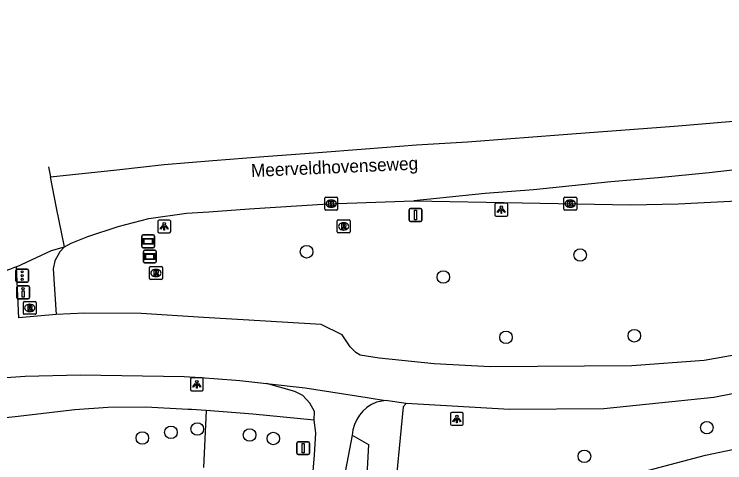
# Model space of a CAD drawing. Extents: x 157663 to 158496, y 379212 to 380934.
# Drawn here: x 158050.2 to 158105.5, y 380860.2 to 380895.1 of the extents above; entities that cross this region are included whole.
import ezdxf

# ---------------------------------------------------------------- set-up
doc = ezdxf.new("R2010")
doc.units = 0
for name, color, linetype in [('IMGEO_Berm_groen', 7, 'Continuous'), ('IMGEO_Boom', 7, 'Continuous'), ('IMGEO_Drukknoppaal', 7, 'Continuous'), ('IMGEO_Fietspad_gesloten', 7, 'Continuous'), ('IMGEO_Kolk', 7, 'Continuous'), ('IMGEO_Lichtpunt', 7, 'Continuous'), ('IMGEO_Openbare_ruimte_label', 7, 'Continuous'), ('IMGEO_Plaatsnaambord', 7, 'Continuous'), ('IMGEO_Rijbaan_regionaal_gesloten', 7, 'Continuous'), ('IMGEO_Rioolput', 7, 'Continuous'), ('IMGEO_Verkeersbordpaal', 7, 'Continuous'), ('IMGEO_Verkeersregelinstallatiepaal', 7, 'Continuous'), ('IMGEO_Voetpad_open', 7, 'Continuous')]:
    doc.layers.add(name, color=color, linetype=linetype)

msp = doc.modelspace()

# ---------------------------------------------------------------- linework, layer by layer
at = {"layer": 'IMGEO_Berm_groen'}
msp.add_lwpolyline([(158065.142, 380864.278), (158064.931, 380859.841)], dxfattribs=at)
at = {"layer": 'IMGEO_Boom'}
for centre in [(158072.959, 380876.644), (158094.236, 380876.394), (158083.597, 380874.678), (158098.449, 380870.11), (158088.471, 380869.981), (158064.452, 380862.854), (158104.093, 380862.957), (158062.405, 380862.587), (158068.523, 380862.386), (158060.18, 380862.153), (158070.369, 380862.108), (158094.569, 380860.723)]:
    msp.add_circle(centre, 0.489, dxfattribs=at)
at = {"layer": 'IMGEO_Drukknoppaal'}
for p, q in [((158050.411, 380873.085), (158050.411, 380873.885)), ((158050.411, 380873.885), (158050.411, 380873.085)), ((158050.511, 380873.985), (158051.301, 380873.985)), ((158051.301, 380873.985), (158050.511, 380873.985)), ((158051.401, 380873.885), (158051.401, 380873.085)), ((158051.401, 380873.085), (158051.401, 380873.885)), ((158051.301, 380872.985), (158050.511, 380872.985)), ((158050.511, 380872.985), (158051.301, 380872.985))]:
    msp.add_line(p, q, dxfattribs=at)
msp.add_lwpolyline([(158050.981, 380873.61), (158050.981, 380873.11), (158050.831, 380873.11), (158050.831, 380873.61), (158050.981, 380873.61)], dxfattribs=at)
msp.add_circle((158050.906, 380873.775), 0.085, dxfattribs=at)
for centre, start, end in [((158050.511, 380873.885), 90, 180), ((158050.511, 380873.885), 90, 180), ((158051.301, 380873.885), 0, 90), ((158051.301, 380873.885), 360, 90), ((158050.511, 380873.085), 180, 270), ((158050.511, 380873.085), 180, 270), ((158051.301, 380873.085), 270, 0), ((158051.301, 380873.085), 270, 0)]:
    msp.add_arc(centre, 0.1, start, end, dxfattribs=at)
at = {"layer": 'IMGEO_Fietspad_gesloten'}
for points in [[(158140.63, 380876.569), (158125.373, 380872.836), (158111.658, 380869.645), (158108.42, 380868.984), (158103.883, 380868.194), (158098.244, 380867.766), (158087.236, 380867.694), (158082.882, 380867.92), (158078.596, 380868.359), (158077.123, 380868.591), (158076.79, 380868.803), (158076.35, 380869.239), (158075.72, 380870.183), (158074.099, 380870.978), (158068.018, 380871.348), (158064.935, 380871.536), (158060.09, 380871.831), (158055.717, 380871.872), (158053.476, 380871.758)], [(158053.476, 380871.758), (158050.571, 380871.497), (158050.393, 380875.474)], [(158141.381, 380873.409), (158125.611, 380869.701), (158120.899, 380868.795), (158112.29, 380866.807), (158104.631, 380865.308), (158096.087, 380864.409), (158088.748, 380864.379), (158080.704, 380864.833)], [(158047.273, 380866.7), (158047.359, 380866.71), (158051.071, 380866.963), (158055.358, 380867.076), (158063.44, 380866.948), (158064.697, 380866.859), (158067.447, 380866.663), (158067.761, 380866.627), (158069.833, 380866.393)], [(158069.833, 380866.393), (158072.835, 380866.05), (158077.671, 380865.297), (158077.813, 380865.268), (158079.105, 380865.074)], [(158073.535, 380863.528), (158073.565, 380864.221), (158073.221, 380864.871), (158072.66, 380865.459), (158072.041, 380865.773), (158069.833, 380866.393)], [(158079.105, 380865.074), (158078.395, 380864.933)], [(158080.704, 380864.833), (158079.105, 380865.074)], [(158072.408, 380844.132), (158072.617, 380849.502), (158073.582, 380860.818), (158073.688, 380862.549), (158073.535, 380863.528)], [(158076.51, 380862.37), (158075.656, 380857.884), (158074.722, 380845.281), (158073.77, 380825.588), (158073.53, 380817.736), (158073.74, 380808.222), (158074.257, 380799.995), (158075.149, 380791.663), (158077.752, 380775.038), (158083.324, 380742.71), (158085.161, 380730.364), (158087.771, 380714.145), (158088.632, 380709.876), (158089.886, 380705.995), (158090.275, 380703.817), (158091.576, 380701.56), (158093.82, 380696.7), (158096.253, 380693.04), (158099.225, 380689.283), (158101.997, 380686.517)]]:
    msp.add_lwpolyline(points, dxfattribs=at)
msp.add_arc((158079.443, 380862.188), 2.938, 110.8894, 176.4442, dxfattribs=at)
at = {"layer": 'IMGEO_Kolk'}
for p, q in [((158074.374, 380879.96), (158074.374, 380880.812)), ((158074.449, 380880.886), (158075.301, 380880.886)), ((158074.862, 380880.666), (158074.887, 380880.666)), ((158075.375, 380880.812), (158075.375, 380879.96)), ((158092.969, 380879.957), (158092.969, 380880.809)), ((158093.044, 380880.883), (158093.896, 380880.883)), ((158093.457, 380880.663), (158093.482, 380880.663)), ((158093.97, 380880.809), (158093.97, 380879.957)), ((158074.885, 380880.106), (158074.86, 380880.106)), ((158093.48, 380880.103), (158093.455, 380880.103)), ((158075.301, 380879.886), (158074.449, 380879.886)), ((158093.896, 380879.883), (158093.044, 380879.883))]:
    msp.add_line(p, q, dxfattribs=at)
for points in [[(158074.374, 380879.96), (158074.374, 380880.812)], [(158074.449, 380880.886), (158075.301, 380880.886)], [(158074.695, 380880.586), (158074.818, 380880.586), (158074.818, 380880.435), (158074.948, 380880.586), (158075.112, 380880.586), (158074.966, 380880.435), (158075.119, 380880.186), (158074.967, 380880.186), (158074.882, 380880.35), (158074.818, 380880.283), (158074.818, 380880.186), (158074.695, 380880.186), (158074.695, 380880.586)], [(158075.375, 380880.812), (158075.375, 380879.96)], [(158092.969, 380879.957), (158092.969, 380880.809)], [(158093.044, 380880.883), (158093.896, 380880.883)], [(158093.29, 380880.583), (158093.413, 380880.583), (158093.413, 380880.432), (158093.543, 380880.583), (158093.707, 380880.583), (158093.561, 380880.432), (158093.714, 380880.183), (158093.562, 380880.183), (158093.477, 380880.347), (158093.413, 380880.28), (158093.413, 380880.183), (158093.29, 380880.183), (158093.29, 380880.583)], [(158093.97, 380880.809), (158093.97, 380879.957)], [(158075.301, 380879.886), (158074.449, 380879.886)], [(158093.896, 380879.883), (158093.044, 380879.883)]]:
    msp.add_lwpolyline(points, dxfattribs=at)
for centre, start, end in [((158074.451, 380880.81), 91.552, 178.448), ((158074.451, 380880.81), 91.552, 178.448), ((158075.299, 380880.81), 1.552, 88.448), ((158075.299, 380880.81), 1.552, 88.448), ((158093.046, 380880.807), 91.552, 178.448), ((158093.046, 380880.807), 91.552, 178.448), ((158093.894, 380880.807), 1.552, 88.448), ((158093.894, 380880.807), 1.552, 88.448), ((158074.451, 380879.962), 181.552, 268.448), ((158074.451, 380879.962), 181.552, 268.448), ((158075.299, 380879.962), 271.552, 358.448), ((158075.299, 380879.962), 271.552, 358.448), ((158093.046, 380879.959), 181.552, 268.448), ((158093.046, 380879.959), 181.552, 268.448), ((158093.894, 380879.959), 271.552, 358.448), ((158093.894, 380879.959), 271.552, 358.448)]:
    msp.add_arc(centre, 0.0765, start, end, dxfattribs=at)
for centre, major_axis, ratio, start_param, end_param in [((158074.861, 380880.386), (-0.387, 0.002), 0.722429, 4.712389, 7.853982), ((158074.886, 380880.386), (-0.39, 0.002), 0.717154, 1.570796, 4.712389), ((158093.456, 380880.383), (-0.387, 0.002), 0.722429, 4.712389, 7.853982), ((158093.481, 380880.383), (-0.39, 0.002), 0.717154, 1.570796, 4.712389)]:
    msp.add_ellipse(centre, major_axis=major_axis, ratio=ratio, start_param=start_param, end_param=end_param, dxfattribs=at)
at = {"layer": 'IMGEO_Lichtpunt'}
for p, q in [((158087.604, 380880.32), (158087.604, 380879.513)), ((158087.604, 380880.32), (158087.604, 380879.513)), ((158088.506, 380880.415), (158087.698, 380880.415)), ((158088.506, 380880.415), (158087.698, 380880.415)), ((158088.6, 380879.513), (158088.6, 380880.32)), ((158088.6, 380879.513), (158088.6, 380880.32)), ((158087.698, 380879.419), (158088.506, 380879.419)), ((158087.698, 380879.419), (158088.506, 380879.419)), ((158061.39, 380879.02), (158061.39, 380878.213)), ((158061.39, 380879.02), (158061.39, 380878.213)), ((158062.292, 380879.115), (158061.484, 380879.115)), ((158062.292, 380879.115), (158061.484, 380879.115)), ((158062.386, 380878.213), (158062.386, 380879.02)), ((158062.386, 380878.213), (158062.386, 380879.02)), ((158061.484, 380878.119), (158062.292, 380878.119)), ((158061.484, 380878.119), (158062.292, 380878.119)), ((158063.924, 380866.731), (158063.924, 380865.924)), ((158063.924, 380866.731), (158063.924, 380865.924)), ((158064.826, 380866.826), (158064.018, 380866.826)), ((158064.826, 380866.826), (158064.018, 380866.826)), ((158064.92, 380865.924), (158064.92, 380866.731)), ((158064.92, 380865.924), (158064.92, 380866.731)), ((158064.018, 380865.83), (158064.826, 380865.83)), ((158064.018, 380865.83), (158064.826, 380865.83)), ((158084.153, 380864.04), (158084.153, 380863.233)), ((158084.153, 380864.04), (158084.153, 380863.233)), ((158085.055, 380864.135), (158084.247, 380864.135)), ((158085.055, 380864.135), (158084.247, 380864.135)), ((158085.149, 380863.233), (158085.149, 380864.04)), ((158085.149, 380863.233), (158085.149, 380864.04)), ((158084.247, 380863.139), (158085.055, 380863.139)), ((158084.247, 380863.139), (158085.055, 380863.139))]:
    msp.add_line(p, q, dxfattribs=at)
for points in [[(158087.978, 380879.984), (158088.017, 380879.956), (158087.829, 380879.694), (158087.791, 380879.721), (158087.978, 380879.984)], [(158088.08, 380879.936), (158088.127, 380879.936), (158088.127, 380879.614), (158088.08, 380879.614), (158088.08, 380879.936)], [(158088.19, 380879.956), (158088.228, 380879.983), (158088.415, 380879.721), (158088.376, 380879.693), (158088.19, 380879.956)], [(158061.764, 380878.684), (158061.803, 380878.656), (158061.615, 380878.394), (158061.577, 380878.421), (158061.764, 380878.684)], [(158061.866, 380878.636), (158061.913, 380878.636), (158061.913, 380878.314), (158061.866, 380878.314), (158061.866, 380878.636)], [(158061.976, 380878.656), (158062.014, 380878.683), (158062.201, 380878.421), (158062.162, 380878.393), (158061.976, 380878.656)], [(158064.298, 380866.395), (158064.337, 380866.367), (158064.149, 380866.105), (158064.111, 380866.132), (158064.298, 380866.395)], [(158064.4, 380866.347), (158064.447, 380866.347), (158064.447, 380866.025), (158064.4, 380866.025), (158064.4, 380866.347)], [(158064.51, 380866.367), (158064.548, 380866.394), (158064.735, 380866.132), (158064.696, 380866.104), (158064.51, 380866.367)], [(158084.527, 380863.704), (158084.566, 380863.676), (158084.378, 380863.414), (158084.34, 380863.441), (158084.527, 380863.704)], [(158084.629, 380863.656), (158084.676, 380863.656), (158084.676, 380863.334), (158084.629, 380863.334), (158084.629, 380863.656)], [(158084.739, 380863.676), (158084.777, 380863.703), (158084.964, 380863.441), (158084.925, 380863.413), (158084.739, 380863.676)]]:
    msp.add_lwpolyline(points, dxfattribs=at)
for centre in [(158088.103, 380880.118), (158061.889, 380878.818), (158064.423, 380866.529), (158084.652, 380863.838)]:
    msp.add_circle(centre, 0.0994, dxfattribs=at)
for centre, start, end in [((158087.698, 380880.32), 90, 180), ((158087.698, 380880.32), 90, 180), ((158088.506, 380880.32), 0, 90), ((158088.506, 380880.32), 0, 90), ((158087.698, 380879.513), 180, 270), ((158087.698, 380879.513), 180, 270), ((158088.506, 380879.513), 270, 0), ((158088.506, 380879.513), 270, 360), ((158061.484, 380879.02), 90, 180), ((158061.484, 380879.02), 90, 180), ((158062.292, 380879.02), 0, 90), ((158062.292, 380879.02), 0, 90), ((158061.484, 380878.213), 180, 270), ((158061.484, 380878.213), 180, 270), ((158062.292, 380878.213), 270, 0), ((158062.292, 380878.213), 270, 360), ((158064.018, 380866.731), 90, 180), ((158064.018, 380866.731), 90, 180), ((158064.826, 380866.731), 0, 90), ((158064.826, 380866.731), 0, 90), ((158064.018, 380865.924), 180, 270), ((158064.018, 380865.924), 180, 270), ((158064.826, 380865.924), 270, 0), ((158064.826, 380865.924), 270, 360), ((158084.247, 380864.04), 90, 180), ((158084.247, 380864.04), 90, 180), ((158085.055, 380864.04), 0, 90), ((158085.055, 380864.04), 0, 90), ((158084.247, 380863.233), 180, 270), ((158084.247, 380863.233), 180, 270), ((158085.055, 380863.233), 270, 0), ((158085.055, 380863.233), 270, 360)]:
    msp.add_arc(centre, 0.0946, start, end, dxfattribs=at)
at = {"layer": 'IMGEO_Plaatsnaambord'}
for p, q in [((158060.144, 380877.055), (158060.144, 380877.855)), ((158060.144, 380877.855), (158060.144, 380877.055)), ((158060.244, 380877.955), (158061.034, 380877.955)), ((158061.034, 380877.955), (158060.244, 380877.955)), ((158061.134, 380877.855), (158061.134, 380877.055)), ((158061.134, 380877.055), (158061.134, 380877.855)), ((158061.034, 380876.955), (158060.244, 380876.955)), ((158060.244, 380876.955), (158061.034, 380876.955)), ((158060.262, 380875.872), (158060.262, 380876.672)), ((158060.262, 380876.672), (158060.262, 380875.872)), ((158060.362, 380876.772), (158061.152, 380876.772)), ((158061.152, 380876.772), (158060.362, 380876.772)), ((158061.252, 380876.672), (158061.252, 380875.872)), ((158061.252, 380875.872), (158061.252, 380876.672)), ((158061.152, 380875.772), (158060.362, 380875.772)), ((158060.362, 380875.772), (158061.152, 380875.772))]:
    msp.add_line(p, q, dxfattribs=at)
for points in [[(158060.245, 380877.687), (158061.033, 380877.687), (158061.033, 380877.223), (158060.245, 380877.223), (158060.245, 380877.687)], [(158060.31, 380877.622), (158060.31, 380877.288), (158060.968, 380877.288), (158060.968, 380877.622), (158060.31, 380877.622)], [(158060.363, 380876.504), (158061.151, 380876.504), (158061.151, 380876.04), (158060.363, 380876.04), (158060.363, 380876.504)], [(158060.428, 380876.439), (158060.428, 380876.105), (158061.086, 380876.105), (158061.086, 380876.439), (158060.428, 380876.439)]]:
    msp.add_lwpolyline(points, dxfattribs=at)
for centre, start, end in [((158060.244, 380877.855), 90, 180), ((158060.244, 380877.855), 90, 180), ((158061.034, 380877.855), 0, 90), ((158061.034, 380877.855), 360, 90), ((158060.244, 380877.055), 180, 270), ((158060.244, 380877.055), 180, 270), ((158060.362, 380876.672), 90, 180), ((158060.362, 380876.672), 90, 180), ((158061.034, 380877.055), 270, 0), ((158061.034, 380877.055), 270, 0), ((158061.152, 380876.672), 0, 90), ((158061.152, 380876.672), 360, 90), ((158060.362, 380875.872), 180, 270), ((158060.362, 380875.872), 180, 270), ((158061.152, 380875.872), 270, 0), ((158061.152, 380875.872), 270, 0)]:
    msp.add_arc(centre, 0.1, start, end, dxfattribs=at)
at = {"layer": 'IMGEO_Rijbaan_regionaal_gesloten'}
for points in [[(158178.332, 380895.132), (158178.311, 380895.13), (158157.971, 380890.35), (158149.175, 380888.767), (158145.241, 380887.993), (158139.469, 380887.076), (158129.602, 380885.619), (158125.792, 380885.125), (158121.91, 380884.621), (158119.805, 380884.419), (158115.871, 380883.958), (158111.93, 380883.562), (158108.098, 380883.225), (158104.277, 380882.779), (158100.307, 380882.396), (158096.616, 380882.09), (158090.617, 380881.474), (158086.85, 380881.18), (158081.303, 380880.598)], [(158053.03, 380882.465), (158058.194, 380883.024), (158061.891, 380883.424), (158065.676, 380883.736), (158069.626, 380884.062), (158073.532, 380884.335), (158077.539, 380884.647), (158081.511, 380884.957), (158085.464, 380885.206), (158093.578, 380885.813), (158101.556, 380886.409), (158109.527, 380887.093), (158113.411, 380887.469), (158117.534, 380887.901), (158121.554, 380888.322), (158125.45, 380888.8), (158129.369, 380889.282), (158133.427, 380889.78), (158137.39, 380890.404), (158142.255, 380891.198)], [(158081.303, 380880.598), (158098.152, 380880.3), (158101.863, 380880.361), (158109.483, 380880.764), (158122.043, 380881.956), (158124.653, 380882.291), (158136.955, 380884.088), (158145.396, 380885.413), (158150.574, 380886.285)], [(158052.871, 380883.253), (158053.03, 380882.465)], [(158054.125, 380877.025), (158053.515, 380880.054), (158053.03, 380882.465)], [(158054.125, 380877.025), (158054.637, 380877.32), (158055.954, 380877.843), (158058.294, 380878.604), (158060.693, 380879.22), (158063.616, 380879.657), (158065.353, 380879.748), (158068.49, 380879.988), (158074.629, 380880.378), (158081.303, 380880.598)], [(158050.393, 380875.474), (158053.104, 380876.743), (158054.125, 380877.025)]]:
    msp.add_lwpolyline(points, dxfattribs=at)
msp.add_arc((158060.903, 380847.435), 29.944, 110.548, 118.2479, dxfattribs=at)
at = {"layer": 'IMGEO_Rioolput'}
for p, q in [((158075.341, 380878.19), (158075.341, 380879.042)), ((158075.416, 380879.116), (158076.268, 380879.116)), ((158075.829, 380878.896), (158075.854, 380878.896)), ((158076.342, 380879.042), (158076.342, 380878.19)), ((158075.852, 380878.336), (158075.827, 380878.336)), ((158076.268, 380878.116), (158075.416, 380878.116)), ((158060.815, 380875.492), (158061.667, 380875.492)), ((158060.74, 380874.566), (158060.74, 380875.418)), ((158061.228, 380875.272), (158061.253, 380875.272)), ((158061.741, 380875.418), (158061.741, 380874.566)), ((158061.667, 380874.492), (158060.815, 380874.492)), ((158061.251, 380874.712), (158061.226, 380874.712)), ((158051.002, 380872.776), (158051.854, 380872.776)), ((158050.927, 380871.85), (158050.927, 380872.702)), ((158051.415, 380872.556), (158051.44, 380872.556)), ((158051.928, 380872.702), (158051.928, 380871.85)), ((158051.854, 380871.776), (158051.002, 380871.776)), ((158051.438, 380871.996), (158051.413, 380871.996))]:
    msp.add_line(p, q, dxfattribs=at)
for points in [[(158075.341, 380878.19), (158075.341, 380879.042)], [(158075.416, 380879.116), (158076.268, 380879.116)], [(158075.93, 380878.814), (158075.678, 380878.816), (158075.678, 380878.416)], [(158076.342, 380879.042), (158076.342, 380878.19)], [(158075.678, 380878.416), (158075.802, 380878.416), (158075.802, 380878.578), (158075.813, 380878.578)], [(158075.856, 380878.735), (158075.802, 380878.735), (158075.802, 380878.654)], [(158075.802, 380878.654), (158075.854, 380878.654)], [(158075.86, 380878.549), (158075.931, 380878.416), (158076.071, 380878.416), (158076.006, 380878.542)], [(158076.268, 380878.116), (158075.416, 380878.116)], [(158060.815, 380875.492), (158061.667, 380875.492)], [(158060.74, 380874.566), (158060.74, 380875.418)], [(158061.329, 380875.19), (158061.077, 380875.192), (158061.077, 380874.792)], [(158061.077, 380874.792), (158061.201, 380874.792), (158061.201, 380874.954), (158061.212, 380874.954)], [(158061.255, 380875.111), (158061.201, 380875.111), (158061.201, 380875.03)], [(158061.201, 380875.03), (158061.253, 380875.03)], [(158061.259, 380874.925), (158061.33, 380874.792), (158061.47, 380874.792), (158061.405, 380874.918)], [(158061.741, 380875.418), (158061.741, 380874.566)], [(158061.667, 380874.492), (158060.815, 380874.492)], [(158051.002, 380872.776), (158051.854, 380872.776)], [(158050.927, 380871.85), (158050.927, 380872.702)], [(158051.516, 380872.474), (158051.264, 380872.476), (158051.264, 380872.076)], [(158051.264, 380872.076), (158051.388, 380872.076), (158051.388, 380872.238), (158051.399, 380872.238)], [(158051.442, 380872.395), (158051.388, 380872.395), (158051.388, 380872.314)], [(158051.388, 380872.314), (158051.44, 380872.314)], [(158051.446, 380872.209), (158051.517, 380872.076), (158051.657, 380872.076), (158051.592, 380872.202)], [(158051.928, 380872.702), (158051.928, 380871.85)], [(158051.854, 380871.776), (158051.002, 380871.776)]]:
    msp.add_lwpolyline(points, dxfattribs=at)
for centre, radius, start, end in [((158075.418, 380879.04), 0.0765, 91.552, 178.448), ((158075.418, 380879.04), 0.0765, 91.552, 178.448), ((158075.929, 380878.704), 0.109, 350.3612, 89.416), ((158076.266, 380879.04), 0.0765, 1.552, 88.448), ((158076.266, 380879.04), 0.0765, 1.552, 88.448), ((158075.812, 380878.525), 0.0533, 26.0293, 88.6989), ((158075.838, 380878.843), 0.19, 274.7715, 282.9687), ((158075.862, 380878.639), 0.0964, 77.0061, 93.1865), ((158075.876, 380878.696), 0.0378, 276.6634, 79.6772), ((158075.927, 380878.704), 0.112, 277.5842, 350.9817), ((158075.911, 380878.489), 0.108, 29.5134, 73.7905), ((158075.418, 380878.192), 0.0765, 181.552, 268.448), ((158075.418, 380878.192), 0.0765, 181.552, 268.448), ((158076.266, 380878.192), 0.0765, 271.552, 358.448), ((158076.266, 380878.192), 0.0765, 271.552, 358.448), ((158060.817, 380875.416), 0.0765, 91.552, 178.448), ((158060.817, 380875.416), 0.0765, 91.552, 178.448), ((158061.665, 380875.416), 0.0765, 1.552, 88.448), ((158061.665, 380875.416), 0.0765, 1.552, 88.448), ((158061.211, 380874.901), 0.0533, 26.0293, 88.6989), ((158061.237, 380875.219), 0.19, 274.7715, 282.9687), ((158061.261, 380875.015), 0.0964, 77.0061, 93.1865), ((158061.275, 380875.072), 0.0378, 276.6634, 79.6772), ((158061.328, 380875.08), 0.109, 350.3612, 89.416), ((158061.326, 380875.08), 0.112, 277.5842, 350.9817), ((158061.31, 380874.865), 0.108, 29.5134, 73.7905), ((158060.817, 380874.568), 0.0765, 181.552, 268.448), ((158060.817, 380874.568), 0.0765, 181.552, 268.448), ((158061.665, 380874.568), 0.0765, 271.552, 358.448), ((158061.665, 380874.568), 0.0765, 271.552, 358.448), ((158051.004, 380872.7), 0.0765, 91.552, 178.448), ((158051.004, 380872.7), 0.0765, 91.552, 178.448), ((158051.852, 380872.7), 0.0765, 1.552, 88.448), ((158051.852, 380872.7), 0.0765, 1.552, 88.448), ((158051.398, 380872.185), 0.0533, 26.0293, 88.6989), ((158051.424, 380872.503), 0.19, 274.7715, 282.9687), ((158051.448, 380872.299), 0.0964, 77.0061, 93.1865), ((158051.462, 380872.356), 0.0378, 276.6634, 79.6772), ((158051.515, 380872.364), 0.109, 350.3612, 89.416), ((158051.513, 380872.364), 0.112, 277.5842, 350.9817), ((158051.497, 380872.149), 0.108, 29.5134, 73.7905), ((158051.004, 380871.852), 0.0765, 181.552, 268.448), ((158051.004, 380871.852), 0.0765, 181.552, 268.448), ((158051.852, 380871.852), 0.0765, 271.552, 358.448), ((158051.852, 380871.852), 0.0765, 271.552, 358.448)]:
    msp.add_arc(centre, radius, start, end, dxfattribs=at)
for centre, major_axis, ratio, start_param, end_param in [((158075.828, 380878.616), (-0.387, 0.002), 0.722429, 4.712389, 7.853982), ((158075.853, 380878.616), (-0.39, 0.002), 0.717154, 1.570796, 4.712389), ((158061.227, 380874.992), (-0.387, 0.002), 0.722429, 4.712389, 7.853982), ((158061.252, 380874.992), (-0.39, 0.002), 0.717154, 1.570796, 4.712389), ((158051.414, 380872.276), (-0.387, 0.002), 0.722429, 4.712389, 7.853982), ((158051.439, 380872.276), (-0.39, 0.002), 0.717154, 1.570796, 4.712389)]:
    msp.add_ellipse(centre, major_axis=major_axis, ratio=ratio, start_param=start_param, end_param=end_param, dxfattribs=at)
at = {"layer": 'IMGEO_Verkeersbordpaal'}
for p, q in [((158080.929, 380879.102), (158080.929, 380879.902)), ((158080.929, 380879.902), (158080.929, 380879.102)), ((158081.029, 380880.002), (158081.819, 380880.002)), ((158081.819, 380880.002), (158081.029, 380880.002)), ((158081.919, 380879.902), (158081.919, 380879.102)), ((158081.919, 380879.102), (158081.919, 380879.902)), ((158081.819, 380879.002), (158081.029, 380879.002)), ((158081.029, 380879.002), (158081.819, 380879.002)), ((158072.2, 380860.958), (158072.2, 380861.758)), ((158072.2, 380861.758), (158072.2, 380860.958)), ((158072.3, 380861.858), (158073.09, 380861.858)), ((158073.09, 380861.858), (158072.3, 380861.858)), ((158073.19, 380861.758), (158073.19, 380860.958)), ((158073.19, 380860.958), (158073.19, 380861.758)), ((158073.09, 380860.858), (158072.3, 380860.858)), ((158072.3, 380860.858), (158073.09, 380860.858))]:
    msp.add_line(p, q, dxfattribs=at)
for points in [[(158081.349, 380879.877), (158081.499, 380879.877), (158081.499, 380879.127), (158081.349, 380879.127), (158081.349, 380879.877)], [(158072.62, 380861.733), (158072.77, 380861.733), (158072.77, 380860.983), (158072.62, 380860.983), (158072.62, 380861.733)]]:
    msp.add_lwpolyline(points, dxfattribs=at)
for centre, start, end in [((158081.029, 380879.902), 90, 180), ((158081.029, 380879.902), 90, 180), ((158081.819, 380879.902), 0, 90), ((158081.819, 380879.902), 360, 90), ((158081.029, 380879.102), 180, 270), ((158081.029, 380879.102), 180, 270), ((158081.819, 380879.102), 270, 0), ((158081.819, 380879.102), 270, 0), ((158072.3, 380861.758), 90, 180), ((158072.3, 380861.758), 90, 180), ((158073.09, 380861.758), 0, 90), ((158073.09, 380861.758), 360, 90), ((158072.3, 380860.958), 180, 270), ((158072.3, 380860.958), 180, 270), ((158073.09, 380860.958), 270, 0), ((158073.09, 380860.958), 270, 0)]:
    msp.add_arc(centre, 0.1, start, end, dxfattribs=at)
at = {"layer": 'IMGEO_Verkeersregelinstallatiepaal'}
for p, q in [((158050.34, 380874.389), (158050.34, 380875.189)), ((158050.34, 380875.189), (158050.34, 380874.389)), ((158050.44, 380875.289), (158051.23, 380875.289)), ((158051.23, 380875.289), (158050.44, 380875.289)), ((158051.33, 380875.189), (158051.33, 380874.389)), ((158051.33, 380874.389), (158051.33, 380875.189)), ((158051.23, 380874.289), (158050.44, 380874.289)), ((158050.44, 380874.289), (158051.23, 380874.289))]:
    msp.add_line(p, q, dxfattribs=at)
for centre in [(158050.835, 380875.079), (158050.835, 380874.789), (158050.835, 380874.499)]:
    msp.add_circle(centre, 0.085, dxfattribs=at)
for centre, start, end in [((158050.44, 380875.189), 90, 180), ((158050.44, 380875.189), 90, 180), ((158051.23, 380875.189), 0, 90), ((158051.23, 380875.189), 360, 90), ((158050.44, 380874.389), 180, 270), ((158050.44, 380874.389), 180, 270), ((158051.23, 380874.389), 270, 0), ((158051.23, 380874.389), 270, 0)]:
    msp.add_arc(centre, 0.1, start, end, dxfattribs=at)
at = {"layer": 'IMGEO_Voetpad_open'}
for points in [[(158054.125, 380877.025), (158053.756, 380876.65), (158053.376, 380875.949), (158053.238, 380875.312), (158053.476, 380871.758)], [(158079.706, 380856.8), (158079.88, 380856.054), (158080.223, 380855.632), (158080.796, 380855.351), (158090.084, 380857.247), (158095.058, 380858.442), (158103.992, 380860.804), (158111.541, 380862.403), (158125.906, 380865.83), (158133.874, 380867.714), (158139.433, 380869.167), (158139.637, 380869.206), (158146.514, 380870.261), (158148.421, 380870.451), (158151.536, 380870.552), (158155.774, 380870.384), (158160.122, 380869.826), (158163.951, 380869.298), (158165.296, 380869.194)], [(158065.142, 380864.278), (158064.009, 380864.36), (158063.756, 380864.378), (158060.455, 380864.554), (158057.495, 380864.527), (158054.928, 380864.342), (158050.301, 380863.802), (158043.877, 380863.111), (158039.322, 380862.715)], [(158080.704, 380864.833), (158080.479, 380864.578), (158079.706, 380856.8)], [(158073.535, 380863.528), (158068.774, 380864.015), (158065.142, 380864.278)], [(158076.51, 380862.37), (158077.768, 380861.65), (158077.399, 380854.931), (158076.565, 380843.437), (158075.894, 380824.951), (158075.551, 380812.413), (158076.033, 380804.062), (158076.731, 380796.337), (158081.843, 380763.329), (158083.93, 380751.483), (158089.326, 380718.53), (158090.58, 380712.063), (158092.023, 380705.933), (158092.55, 380703.495), (158098.681, 380695.497), (158101.641, 380691.985), (158104.362, 380689.226)]]:
    msp.add_lwpolyline(points, dxfattribs=at)

# ---------------------------------------------------------------- texts
at = {"layer": 'IMGEO_Openbare_ruimte_label'}
msp.add_text('Meerveldhovenseweg', height=1, rotation=2.5791, dxfattribs=at).set_placement((158068.658, 380882.457))

doc.saveas('drawing.dxf')
